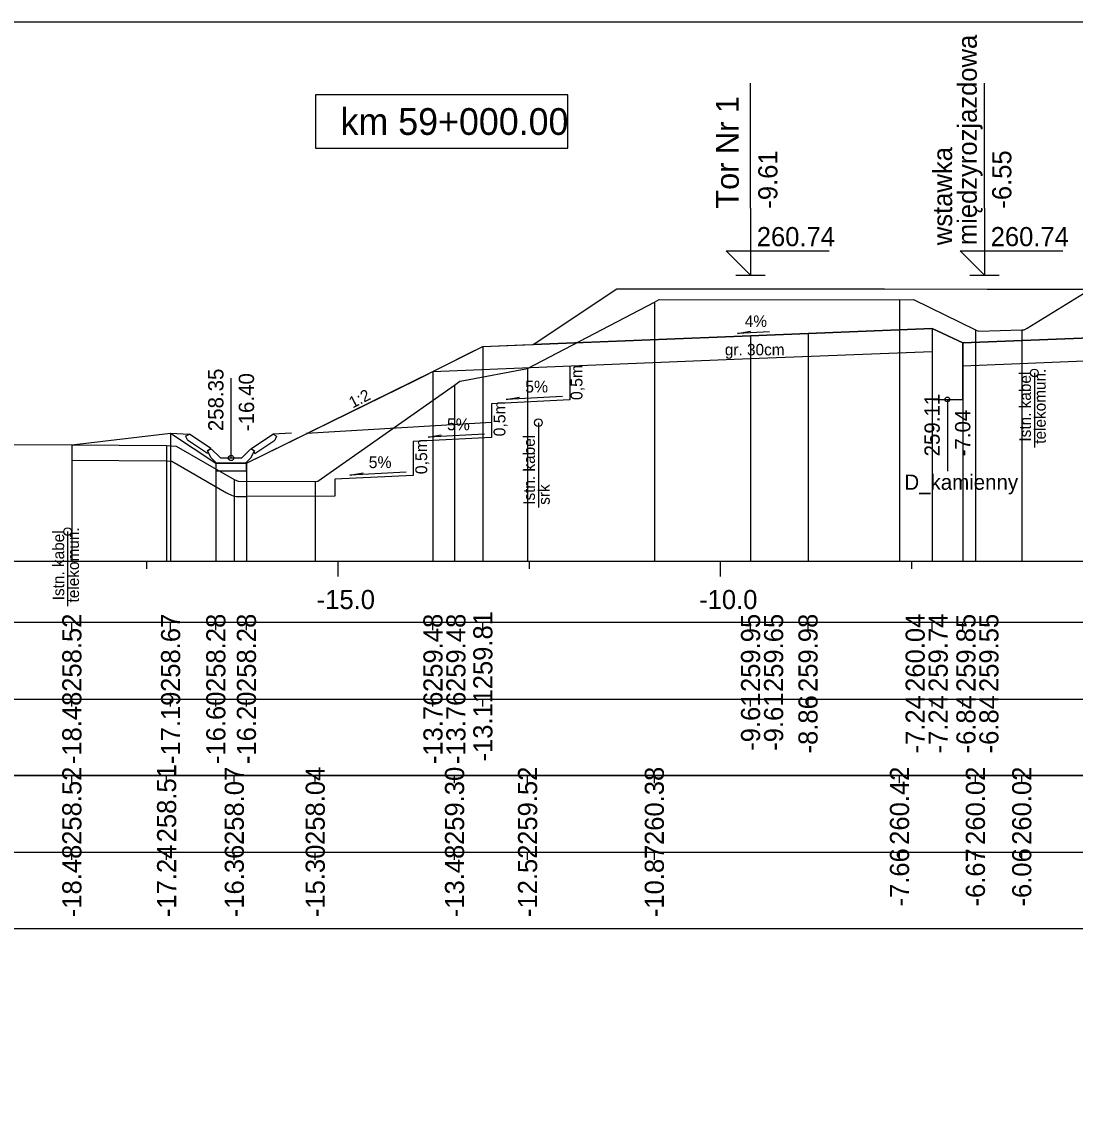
# Model space of a CAD drawing. Extents: x 6516023 to 6560129, y 5513077 to 5529206.
# Drawn here: x 6517204.08 to 6517217.85, y 5514565.91 to 5514580.16 of the extents above; entities that cross this region are included whole.
import ezdxf

# ---------------------------------------------------------------- set-up
doc = ezdxf.new("R2010")
doc.units = 0
for name, color, linetype in [('IR_default', 7, 'Continuous'), ('TOR_PRZEK_P-kable', 7, 'Continuous'), ('TOR_PRZEK_P-komponent', 7, 'Continuous'), ('TOR_PRZEK_P-odwodnienie', 7, 'Continuous'), ('TOR_PRZEK_P-opisy', 7, 'Continuous'), ('TOR_PRZEK_P-schodkowanie+wymiana', 7, 'Continuous'), ('TOR_PRZEK_P-tabelka istniejace', 7, 'Continuous'), ('TOR_PRZEK_P-tabelka projektowane', 7, 'Continuous'), ('TOR_PRZEK_P-teren istniejacy', 7, 'Continuous'), ('TOR_PRZEK_P-tory projektowane', 7, 'Continuous'), ('TOR_PRZEK_P-uklad odniesienia', 7, 'Continuous'), ('TOR_PRZEK_P-warstwa ochronna I', 7, 'Continuous'), ('TOR_PRZEK_P-warstwa ochronna II', 7, 'Continuous'), ('TOR_PS_T-skarpy projektowane', 7, 'Continuous'), ('TOR_RAMKI-ramka+tabelka 1', 7, 'Continuous')]:
    doc.layers.add(name, color=color, linetype=linetype)

msp = doc.modelspace()

# ---------------------------------------------------------------- linework, layer by layer
at = {"layer": 'IR_default'}
msp.add_lwpolyline([(6517204.731, 5514574.628), (6517206.022, 5514574.781), (6517206.613, 5514574.386), (6517207.013, 5514574.386), (6517209.235, 5514575.479), (6517209.235, 5514575.479), (6517209.927, 5514575.825), (6517210.105, 5514575.914), (6517210.629, 5514575.935), (6517210.763, 5514575.94), (6517211.632, 5514576.519), (6517211.855, 5514576.668), (6517214.641, 5514576.667), (6517215.355, 5514576.667), (6517216.698, 5514576.664), (6517216.963, 5514576.663), (6517217.676, 5514576.663), (6517220.463, 5514576.664)], dxfattribs=at)
at = {"layer": 'TOR_PRZEK_P-kable'}
for p, q in [((6517217.314, 5514575.568), (6517217.314, 5514574.594)), ((6517210.83, 5514574.917), (6517210.83, 5514573.807)), ((6517204.676, 5514573.494), (6517204.676, 5514572.52))]:
    msp.add_line(p, q, dxfattribs=at)
for centre in [(6517217.314, 5514575.568), (6517210.83, 5514574.917), (6517204.676, 5514573.494)]:
    msp.add_circle(centre, 0.05, dxfattribs=at)
at = {"layer": 'TOR_PRZEK_P-komponent'}
msp.add_lwpolyline([(6517211.855, 5514576.668), (6517215.355, 5514576.667), (6517216.963, 5514576.663), (6517220.463, 5514576.664), (6517221.463, 5514576.664), (6517224.963, 5514576.664), (6517225.513, 5514576.664), (6517229.013, 5514576.664), (6517230.357, 5514575.768), (6517226.513, 5514575.922), (6517223.213, 5514576.054), (6517222.463, 5514576.084), (6517221.263, 5514576.132), (6517220.663, 5514576.132), (6517219.463, 5514576.084), (6517218.713, 5514576.054), (6517216.377, 5514575.96), (6517215.977, 5514576.149), (6517214.355, 5514576.084), (6517213.605, 5514576.054), (6517210.763, 5514575.94)], close=True, dxfattribs=at)
at = {"layer": 'TOR_PRZEK_P-odwodnienie'}
for p, q in [((6517206.813, 5514574.456), (6517206.813, 5514575.5)), ((6517216.177, 5514575.221), (6517216.177, 5514574.283)), ((6517206.548, 5514574.582), (6517206.268, 5514574.769)), ((6517207.078, 5514574.582), (6517207.358, 5514574.769)), ((6517206.504, 5514574.515), (6517206.243, 5514574.69)), ((6517207.122, 5514574.515), (6517207.383, 5514574.69)), ((6517206.515, 5514574.532), (6517206.504, 5514574.515)), ((6517206.506, 5514574.551), (6517206.553, 5514574.575)), ((6517206.548, 5514574.582), (6517206.54, 5514574.569)), ((6517206.673, 5514574.456), (6517206.553, 5514574.575)), ((6517206.673, 5514574.456), (6517206.953, 5514574.456)), ((6517206.953, 5514574.456), (6517207.073, 5514574.575)), ((6517207.073, 5514574.575), (6517207.121, 5514574.551)), ((6517207.078, 5514574.582), (6517207.086, 5514574.569)), ((6517207.111, 5514574.532), (6517207.122, 5514574.515)), ((6517206.623, 5514574.386), (6517207.003, 5514574.386))]:
    msp.add_line(p, q, dxfattribs=at)
for points in [[(6517215.977, 5514576.149), (6517215.977, 5514575.221), (6517216.377, 5514575.221), (6517216.377, 5514575.96)], [(6517206.022, 5514574.781), (6517206.268, 5514574.769)], [(6517206.218, 5514574.742), (6517206.268, 5514574.769)], [(6517206.218, 5514574.742), (6517206.243, 5514574.69)], [(6517207.604, 5514574.781), (6517207.358, 5514574.769)], [(6517207.408, 5514574.742), (6517207.358, 5514574.769)], [(6517207.408, 5514574.742), (6517207.383, 5514574.69)], [(6517206.54, 5514574.569), (6517206.505, 5514574.551)], [(6517206.505, 5514574.551), (6517206.515, 5514574.532)], [(6517206.553, 5514574.456), (6517206.506, 5514574.551)], [(6517206.623, 5514574.386), (6517206.553, 5514574.456)], [(6517207.003, 5514574.386), (6517207.073, 5514574.456)], [(6517207.073, 5514574.456), (6517207.121, 5514574.551)], [(6517207.086, 5514574.569), (6517207.121, 5514574.551)], [(6517207.121, 5514574.551), (6517207.111, 5514574.532)], [(6517207.013, 5514574.386), (6517206.613, 5514574.386), (6517206.613, 5514574.286), (6517207.013, 5514574.286), (6517207.013, 5514574.386)]]:
    msp.add_lwpolyline(points, dxfattribs=at)
for centre, radius in [((6517216.177, 5514575.221), 0.03), ((6517206.813, 5514574.456), 0.035)]:
    msp.add_circle(centre, radius, dxfattribs=at)
at = {"layer": 'TOR_PRZEK_P-opisy'}
msp.add_lwpolyline([(6517213.852, 5514576.103), (6517213.434, 5514576.084), (6517213.602, 5514576.112)], dxfattribs=at)
at = {"layer": 'TOR_PRZEK_P-schodkowanie+wymiana'}
for p, q in [((6517211.24, 5514575.659), (6517211.24, 5514575.216)), ((6517211.24, 5514575.216), (6517210.217, 5514575.165)), ((6517210.217, 5514575.165), (6517210.217, 5514574.722)), ((6517210.217, 5514574.92), (6517207.797, 5514574.777)), ((6517210.217, 5514574.722), (6517209.194, 5514574.671)), ((6517209.194, 5514574.671), (6517209.194, 5514574.228)), ((6517209.194, 5514574.228), (6517208.171, 5514574.177)), ((6517208.171, 5514574.177), (6517208.171, 5514573.955)), ((6517208.171, 5514573.955), (6517207.013, 5514573.951))]:
    msp.add_line(p, q, dxfattribs=at)
at = {"layer": 'TOR_PRZEK_P-tabelka istniejace'}
for p, q in [((6517204.731, 5514570.206), (6517204.731, 5514570.306)), ((6517205.97, 5514570.206), (6517205.97, 5514570.306)), ((6517206.855, 5514570.206), (6517206.855, 5514570.306)), ((6517207.913, 5514570.206), (6517207.913, 5514570.306)), ((6517209.734, 5514570.206), (6517209.734, 5514570.306)), ((6517210.689, 5514570.206), (6517210.689, 5514570.306)), ((6517212.346, 5514570.206), (6517212.346, 5514570.306)), ((6517215.551, 5514570.206), (6517215.551, 5514570.306)), ((6517216.543, 5514570.206), (6517216.543, 5514570.306)), ((6517217.149, 5514570.206), (6517217.149, 5514570.306)), ((6517182.163, 5514569.306), (6517265.963, 5514569.306)), ((6517204.731, 5514569.206), (6517204.731, 5514569.306)), ((6517205.97, 5514569.206), (6517205.97, 5514569.306)), ((6517206.855, 5514569.206), (6517206.855, 5514569.306)), ((6517207.913, 5514569.206), (6517207.913, 5514569.306)), ((6517209.734, 5514569.206), (6517209.734, 5514569.306)), ((6517210.689, 5514569.206), (6517210.689, 5514569.306)), ((6517212.346, 5514569.206), (6517212.346, 5514569.306)), ((6517215.551, 5514569.206), (6517215.551, 5514569.306)), ((6517216.543, 5514569.206), (6517216.543, 5514569.306)), ((6517217.149, 5514569.206), (6517217.149, 5514569.306))]:
    msp.add_line(p, q, dxfattribs=at)
for points in [[(6517212.346, 5514576.491), (6517212.346, 5514573.306), (6517212.346, 5514573.176), (6517212.346, 5514573.106)], [(6517215.551, 5514576.524), (6517215.551, 5514573.306), (6517215.551, 5514573.176), (6517215.551, 5514573.106)], [(6517216.543, 5514576.129), (6517216.543, 5514573.306), (6517216.543, 5514573.176), (6517216.543, 5514573.106)], [(6517217.149, 5514576.13), (6517217.149, 5514573.306), (6517217.149, 5514573.176), (6517217.149, 5514573.106)], [(6517210.689, 5514575.626), (6517210.689, 5514573.306), (6517210.689, 5514573.176), (6517210.689, 5514573.106)], [(6517209.734, 5514575.409), (6517209.734, 5514573.306), (6517209.734, 5514573.176), (6517209.734, 5514573.106)], [(6517204.731, 5514574.628), (6517204.731, 5514573.306), (6517204.731, 5514573.176), (6517204.731, 5514573.106)], [(6517205.97, 5514574.619), (6517205.97, 5514573.306), (6517205.97, 5514573.176), (6517205.97, 5514573.106)], [(6517206.855, 5514574.174), (6517206.855, 5514573.306), (6517206.855, 5514573.176), (6517206.855, 5514573.106)], [(6517207.913, 5514574.148), (6517207.913, 5514573.306), (6517207.913, 5514573.176), (6517207.913, 5514573.106)]]:
    msp.add_lwpolyline(points, dxfattribs=at)
msp.add_lwpolyline([(6517182.163, 5514570.306), (6517182.163, 5514568.306), (6517265.963, 5514568.306), (6517265.963, 5514570.306)], close=True, dxfattribs=at)
at = {"layer": 'TOR_PRZEK_P-tabelka projektowane'}
for p, q in [((6517204.731, 5514572.206), (6517204.731, 5514572.306)), ((6517206.022, 5514572.206), (6517206.022, 5514572.306)), ((6517206.613, 5514572.206), (6517206.613, 5514572.306)), ((6517207.013, 5514572.206), (6517207.013, 5514572.306)), ((6517209.452, 5514572.206), (6517209.452, 5514572.306)), ((6517209.452, 5514572.206), (6517209.452, 5514572.306)), ((6517210.104, 5514572.206), (6517210.104, 5514572.306)), ((6517213.604, 5514572.206), (6517213.604, 5514572.306)), ((6517213.605, 5514572.206), (6517213.605, 5514572.306)), ((6517214.355, 5514572.206), (6517214.355, 5514572.306)), ((6517215.977, 5514572.206), (6517215.977, 5514572.306)), ((6517216.377, 5514572.206), (6517216.377, 5514572.306)), ((6517182.163, 5514571.306), (6517265.963, 5514571.306)), ((6517204.731, 5514571.206), (6517204.731, 5514571.306)), ((6517206.022, 5514571.206), (6517206.022, 5514571.306)), ((6517206.613, 5514571.206), (6517206.613, 5514571.306)), ((6517207.013, 5514571.206), (6517207.013, 5514571.306)), ((6517209.452, 5514571.206), (6517209.452, 5514571.306)), ((6517209.452, 5514571.206), (6517209.452, 5514571.306)), ((6517210.104, 5514571.206), (6517210.104, 5514571.306)), ((6517213.604, 5514571.206), (6517213.604, 5514571.306)), ((6517213.605, 5514571.206), (6517213.605, 5514571.306)), ((6517214.355, 5514571.206), (6517214.355, 5514571.306)), ((6517215.977, 5514571.206), (6517215.977, 5514571.306)), ((6517216.377, 5514571.206), (6517216.377, 5514571.306))]:
    msp.add_line(p, q, dxfattribs=at)
for points in [[(6517213.604, 5514576.054), (6517213.604, 5514573.306), (6517213.604, 5514573.176), (6517213.604, 5514573.106)], [(6517214.355, 5514576.084), (6517214.355, 5514573.306), (6517214.355, 5514573.176), (6517214.355, 5514573.106)], [(6517215.977, 5514576.149), (6517215.977, 5514573.306), (6517215.977, 5514573.176), (6517215.977, 5514573.106)], [(6517210.104, 5514575.914), (6517210.104, 5514573.306), (6517210.104, 5514573.176), (6517210.104, 5514573.106)], [(6517216.377, 5514575.96), (6517216.377, 5514573.306), (6517216.377, 5514573.176), (6517216.377, 5514573.106)], [(6517213.605, 5514575.754), (6517213.605, 5514573.306), (6517213.605, 5514573.176), (6517213.605, 5514573.106)], [(6517215.977, 5514575.849), (6517215.977, 5514573.306), (6517215.977, 5514573.176), (6517215.977, 5514573.106)], [(6517209.452, 5514575.588), (6517209.452, 5514573.306), (6517209.452, 5514573.176), (6517209.452, 5514573.106)], [(6517209.452, 5514575.588), (6517209.452, 5514573.306), (6517209.452, 5514573.176), (6517209.452, 5514573.106)], [(6517216.377, 5514575.66), (6517216.377, 5514573.306), (6517216.377, 5514573.176), (6517216.377, 5514573.106)], [(6517206.022, 5514574.781), (6517206.022, 5514573.306), (6517206.022, 5514573.176), (6517206.022, 5514573.106)], [(6517204.731, 5514574.628), (6517204.731, 5514573.306), (6517204.731, 5514573.176), (6517204.731, 5514573.106)], [(6517206.613, 5514574.386), (6517206.613, 5514573.306), (6517206.613, 5514573.176), (6517206.613, 5514573.106)], [(6517207.013, 5514574.386), (6517207.013, 5514573.306), (6517207.013, 5514573.176), (6517207.013, 5514573.106)]]:
    msp.add_lwpolyline(points, dxfattribs=at)
msp.add_lwpolyline([(6517182.163, 5514572.306), (6517182.163, 5514570.306), (6517265.963, 5514570.306), (6517265.963, 5514572.306)], close=True, dxfattribs=at)
at = {"layer": 'TOR_PRZEK_P-teren istniejacy'}
msp.add_lwpolyline([(6517199.552, 5514574.637), (6517204.731, 5514574.628), (6517205.97, 5514574.619), (6517206.095, 5514574.611), (6517206.855, 5514574.174), (6517206.904, 5514574.151), (6517207.913, 5514574.148), (6517207.945, 5514574.151), (6517209.734, 5514575.409), (6517209.805, 5514575.458), (6517209.854, 5514575.469), (6517210.689, 5514575.626), (6517212.346, 5514576.491), (6517212.411, 5514576.529), (6517215.551, 5514576.524), (6517215.735, 5514576.529), (6517216.543, 5514576.129), (6517216.583, 5514576.114), (6517217.149, 5514576.13), (6517217.18, 5514576.131), (6517217.222, 5514576.152), (6517218.069, 5514576.676)], dxfattribs=at)
at = {"layer": 'TOR_PRZEK_P-tory projektowane'}
for p, q in [((6517213.605, 5514577.721), (6517213.605, 5514579.354)), ((6517216.663, 5514577.721), (6517216.663, 5514579.354)), ((6517213.605, 5514577.721), (6517213.605, 5514576.844)), ((6517216.663, 5514577.721), (6517216.663, 5514576.844)), ((6517213.605, 5514576.844), (6517213.285, 5514577.163)), ((6517213.285, 5514577.163), (6517214.63, 5514577.163)), ((6517216.663, 5514576.844), (6517216.344, 5514577.163)), ((6517216.344, 5514577.163), (6517217.688, 5514577.163)), ((6517213.413, 5514576.844), (6517213.796, 5514576.844)), ((6517216.471, 5514576.844), (6517216.855, 5514576.844))]:
    msp.add_line(p, q, dxfattribs=at)
at = {"layer": 'TOR_PRZEK_P-uklad odniesienia'}
for p, q in [((6517185.963, 5514573.106), (6517265.963, 5514573.106)), ((6517205.713, 5514573.006), (6517205.713, 5514573.106)), ((6517208.213, 5514572.906), (6517208.213, 5514573.106)), ((6517210.713, 5514573.006), (6517210.713, 5514573.106)), ((6517213.213, 5514572.906), (6517213.213, 5514573.106)), ((6517215.713, 5514573.006), (6517215.713, 5514573.106))]:
    msp.add_line(p, q, dxfattribs=at)
msp.add_lwpolyline([(6517211.216, 5514579.203), (6517207.916, 5514579.203), (6517207.916, 5514578.503), (6517211.216, 5514578.503)], close=True, dxfattribs=at)
at = {"layer": 'TOR_PRZEK_P-warstwa ochronna I'}
for points in [[(6517209.452, 5514575.588), (6517213.605, 5514575.754), (6517215.977, 5514575.849)], [(6517216.377, 5514575.66), (6517218.713, 5514575.754), (6517219.463, 5514575.784), (6517220.663, 5514575.832), (6517221.263, 5514575.832), (6517222.463, 5514575.784), (6517223.213, 5514575.754), (6517226.513, 5514575.622), (6517227.263, 5514575.592), (6517232.215, 5514575.394)]]:
    msp.add_lwpolyline(points, dxfattribs=at)
at = {"layer": 'TOR_PRZEK_P-warstwa ochronna II'}
msp.add_lwpolyline([(6517204.731, 5514574.628), (6517206.022, 5514574.781), (6517206.613, 5514574.386), (6517207.013, 5514574.386), (6517209.452, 5514575.588), (6517210.104, 5514575.914), (6517213.604, 5514576.054), (6517214.355, 5514576.084), (6517215.977, 5514576.149), (6517216.377, 5514575.96), (6517218.713, 5514576.054), (6517219.463, 5514576.084), (6517220.663, 5514576.132), (6517221.263, 5514576.132), (6517222.463, 5514576.084), (6517223.213, 5514576.054), (6517226.513, 5514575.922), (6517227.263, 5514575.892), (6517231.563, 5514575.72), (6517232.433, 5514575.285), (6517234.594, 5514574.204), (6517234.994, 5514574.204), (6517235.586, 5514574.598), (6517238.217, 5514574.651)], dxfattribs=at)
at = {"layer": 'TOR_PS_T-skarpy projektowane'}
for p, q in [((6517206.77, 5514573.993), (6517206.818, 5514573.97)), ((6517206.903, 5514573.951), (6517207.013, 5514573.951))]:
    msp.add_line(p, q, dxfattribs=at)
for points in [[(6517211.146, 5514575.261), (6517210.411, 5514575.221), (6517210.584, 5514575.252)], [(6517210.124, 5514574.766), (6517209.388, 5514574.727), (6517209.561, 5514574.758)], [(6517204.731, 5514574.428), (6517205.963, 5514574.42), (6517206.036, 5514574.415), (6517206.755, 5514574.001)], [(6517209.101, 5514574.272), (6517208.366, 5514574.233), (6517208.538, 5514574.263)]]:
    msp.add_lwpolyline(points, dxfattribs=at)
for centre, start, end in [((6517206.855, 5514574.174), 240.1025, 244.68), ((6517206.904, 5514574.151), 244.68, 269.8267)]:
    msp.add_arc(centre, 0.2, start, end, dxfattribs=at)
at = {"layer": 'TOR_RAMKI-ramka+tabelka 1'}
msp.add_lwpolyline([(6517179.513, 5514580.156), (6517427.013, 5514580.156), (6517427.013, 5514551.656), (6517179.513, 5514551.656)], close=True, dxfattribs=at)

# ---------------------------------------------------------------- texts
at = {"layer": 'TOR_PRZEK_P-kable'}
for s, height, p in [('telekomun.', 0.15, (6517217.463, 5514574.642)), ('Istn. kabel', 0.14999, (6517217.269, 5514574.67)), ('Istn. kabel', 0.14999, (6517210.785, 5514573.844)), ('srk', 0.15, (6517210.979, 5514573.844)), ('Istn. kabel', 0.14999, (6517204.631, 5514572.596)), ('telekomun.', 0.15, (6517204.825, 5514572.568))]:
    msp.add_text(s, height=height, rotation=90.0511, dxfattribs=at).set_placement(p)
at = {"layer": 'TOR_PRZEK_P-odwodnienie'}
for s, rotation, p in [('258.35', 90, (6517206.713, 5514574.806)), ('-16.40', 90, (6517207.113, 5514574.806)), ('259.11', 90, (6517216.077, 5514574.477)), ('-7.04', 90, (6517216.477, 5514574.477)), ('D_kamienny', 360, (6517215.615, 5514574.04))]:
    msp.add_text(s, height=0.2, rotation=rotation, dxfattribs=at).set_placement(p)
at = {"layer": 'TOR_PRZEK_P-opisy'}
for s, rotation, p in [('4%', 0.1515, (6517213.529, 5514576.168)), ('1:2', 27.0701, (6517208.401, 5514575.102))]:
    msp.add_text(s, height=0.15, rotation=rotation, dxfattribs=at).set_placement(p)
at = {"layer": 'TOR_PRZEK_P-schodkowanie+wymiana'}
for p in [(6517211.406, 5514575.213), (6517210.399, 5514574.738), (6517209.376, 5514574.244)]:
    msp.add_text('0,5m', height=0.1545, rotation=90, dxfattribs=at).set_placement(p)
at = {"layer": 'TOR_PRZEK_P-tabelka istniejace'}
for s, p in [('258.52', (6517204.856, 5514569.4)), ('258.51', (6517206.095, 5514569.433)), ('258.07', (6517206.98, 5514569.398)), ('258.04', (6517208.038, 5514569.399)), ('259.30', (6517209.859, 5514569.398)), ('259.52', (6517210.814, 5514569.4)), ('260.38', (6517212.471, 5514569.398)), ('260.42', (6517215.676, 5514569.4)), ('260.02', (6517216.668, 5514569.4)), ('260.02', (6517217.274, 5514569.4)), ('-18.48', (6517204.856, 5514568.454)), ('-17.24', (6517206.095, 5514568.455)), ('-16.36', (6517206.98, 5514568.454)), ('-15.30', (6517208.038, 5514568.455)), ('-13.48', (6517209.859, 5514568.454)), ('-12.52', (6517210.814, 5514568.456)), ('-10.87', (6517212.471, 5514568.455)), ('-7.66', (6517215.676, 5514568.594)), ('-6.67', (6517216.668, 5514568.594)), ('-6.06', (6517217.274, 5514568.594))]:
    msp.add_text(s, height=0.25, rotation=90, dxfattribs=at).set_placement(p)
at = {"layer": 'TOR_PRZEK_P-tabelka projektowane'}
for s, p in [('258.52', (6517204.856, 5514571.4)), ('258.67', (6517206.147, 5514571.398)), ('258.28', (6517206.738, 5514571.398)), ('258.28', (6517207.138, 5514571.398)), ('259.48', (6517209.577, 5514571.398)), ('259.48', (6517209.877, 5514571.398)), ('259.81', (6517210.229, 5514571.433)), ('259.95', (6517213.729, 5514571.397)), ('259.65', (6517214.03, 5514571.397)), ('259.98', (6517214.48, 5514571.398)), ('260.04', (6517215.881, 5514571.399)), ('259.74', (6517216.181, 5514571.399)), ('259.85', (6517216.545, 5514571.397)), ('259.55', (6517216.845, 5514571.397)), ('-18.48', (6517204.856, 5514570.454)), ('-17.19', (6517206.147, 5514570.455)), ('-16.60', (6517206.738, 5514570.455)), ('-16.20', (6517207.138, 5514570.455)), ('-13.76', (6517209.577, 5514570.454)), ('-13.76', (6517209.877, 5514570.454)), ('-13.11', (6517210.229, 5514570.489)), ('-9.61', (6517213.729, 5514570.629)), ('-9.61', (6517214.03, 5514570.629)), ('-8.86', (6517214.48, 5514570.594)), ('-7.24', (6517215.881, 5514570.595)), ('-7.24', (6517216.181, 5514570.595)), ('-6.84', (6517216.545, 5514570.595)), ('-6.84', (6517216.845, 5514570.595))]:
    msp.add_text(s, height=0.25, rotation=90, dxfattribs=at).set_placement(p)
at = {"layer": 'TOR_PRZEK_P-tory projektowane'}
for s, height, p in [('międzyrozjazdowa', 0.25, (6517216.562, 5514577.237)), ('Tor Nr 1', 0.3, (6517213.45, 5514577.715)), ('-9.61', 0.25, (6517213.955, 5514577.714)), ('wstawka', 0.25, (6517216.239, 5514577.237)), ('-6.55', 0.25, (6517217.013, 5514577.714))]:
    msp.add_text(s, height=height, rotation=90, dxfattribs=at).set_placement(p)
for p in [(6517213.685, 5514577.224), (6517216.743, 5514577.224)]:
    msp.add_text('260.74', height=0.25, dxfattribs=at).set_placement(p)
at = {"layer": 'TOR_PRZEK_P-uklad odniesienia'}
for s, height, p in [('km 59+000.00', 0.35, (6517208.244, 5514578.678)), ('-15.0', 0.25, (6517207.932, 5514572.481)), ('-10.0', 0.25, (6517212.932, 5514572.481))]:
    msp.add_text(s, height=height, dxfattribs=at).set_placement(p)
at = {"layer": 'TOR_PRZEK_P-warstwa ochronna I'}
msp.add_text('gr. 30cm', height=0.15, dxfattribs=at).set_placement((6517213.268, 5514575.797))
at = {"layer": 'TOR_PS_T-skarpy projektowane'}
for p in [(6517210.658, 5514575.312), (6517209.635, 5514574.818), (6517208.612, 5514574.324)]:
    msp.add_text('5%', height=0.1545, dxfattribs=at).set_placement(p)

doc.saveas('drawing.dxf')
